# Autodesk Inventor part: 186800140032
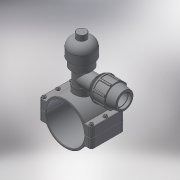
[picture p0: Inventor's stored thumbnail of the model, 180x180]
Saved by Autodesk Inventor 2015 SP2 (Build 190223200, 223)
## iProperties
Created: 2017-05
Part Number: 186800140032
Material: Generic
Description: PLASSON MECHANICAL TAPPING VALVE 140-32
Document SubType Name: Modeling
Designer: KIM
Density: 1 g/cm^3
Appearance: Default
Author: KIM
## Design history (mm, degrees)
derived "18680.ipt"
feature "Solid1::18680.ipt"
feature "Solid2::18680.ipt"
tag "TaggingFeature1"
body "Solid1"
other parameters: "d0" = 154, "d1" = 201, "d4" = 136, "d5" = 0, "d6" = 10.05, "d7" = 201, "d8" = 0.1, "d10" = 0, "d11" = 1.4, "d14" = 50.6376, "d20" = 1.4, "d23" = 1.4, "d36" = 15, "d37" = 12, "d38" = 78, "d39" = 0, "d40" = 3, "d41" = 5, "d42" = 0, "d44" = 3, "d45" = 0, "d46" = 1.4, "d51" = 106, "d52" = 38.952, "d53" = 25, "d54" = 0, "d55" = 32, "d57" = 0, "d58" = 151.2, "d60" = 0, "d62" = 15, "d63" = 12, "d66" = 112, "d67" = 32, "d68" = 11.25, "d69" = 27, "d70" = 64, "d71" = 48, "d72" = 1.92857, "d73" = 51.2, "d74" = 120 deg, "d75" = 48, "d76" = 10 deg, "d77" = 57.6, "d78" = 40.5, "d79" = 67, "d80" = 25.6, "d81" = 135, "d82" = 6.7, "d87" = 19.28571, "d90" = 59.52, "d91" = 35 deg, "d92" = 17.5 deg, "d94" = 0, "d96" = 360 deg, "d98" = 0.64, "d99" = 73.7, "d100" = 38.4, "d101" = 135 deg, "d102" = 1.28, "d105" = 3.2, "d106" = 0, "d107" = 0.1, "d109" = 50.6376, "d112" = 34.85714, "d113" = 4.5, "d116" = 0, "d121" = 46.7424, "d122" = 77.904, "d123" = 66.2184, "d124" = 45 deg, "d125" = 219.6, "d126" = 244, "d127" = 146.4, "d128" = 1, "B_" = 32, "G_" = 38.952, "A_" = 106, "L_" = 201, "L_1" = 136, "l_2" = 25, "d_1" = 32, "E_" = 64, "l_" = 67, "H_" = 135, "H_2" = 244
